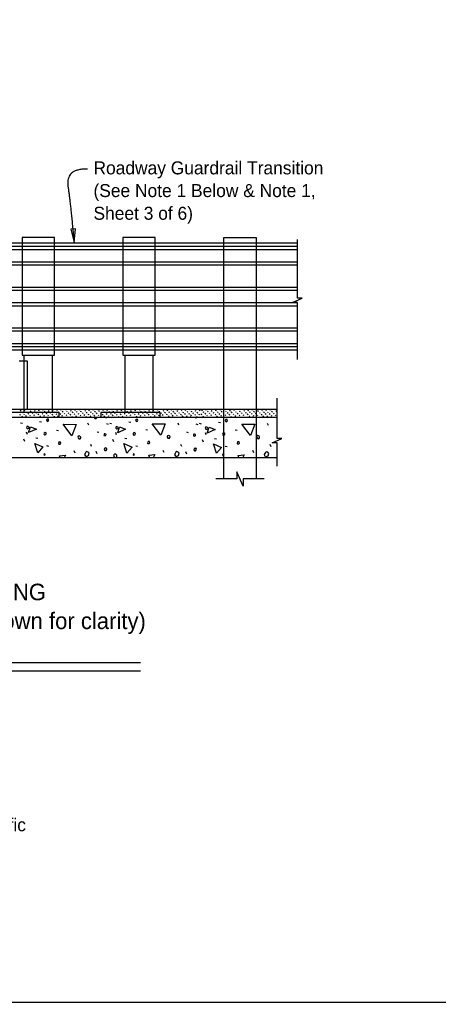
# Model space of a CAD drawing. Extents: x 1.5 to 68.7, y 0 to 31.1.
# Drawn here: x 14.15 to 20.65, y 1.78 to 17.03 of the extents above; entities that cross this region are included whole.
import ezdxf

# ---------------------------------------------------------------- set-up
doc = ezdxf.new("R2010")
doc.units = 0
for name, color, linetype in [('ActivePts-ConstElements', 7, 'Continuous'), ('AdhocPoint_dp', 7, 'Continuous'), ('Patterning', 7, 'Continuous'), ('PlotBorder_dp', 7, 'Continuous')]:
    doc.layers.add(name, color=color, linetype=linetype)

msp = doc.modelspace()

# ---------------------------------------------------------------- linework, layer by layer
at = {"layer": 'ActivePts-ConstElements'}
msp.add_lwpolyline([(1.467, 28.183), (42.533, 28.183), (42.533, 1.783), (1.467, 1.783)], close=True, dxfattribs=at)
at = {"layer": 'AdhocPoint_dp'}
for p, q in [((12.038, 7.055), (16.027, 7.055)), ((12.038, 6.925), (16.027, 6.925))]:
    msp.add_line(p, q, dxfattribs=at)
msp.add_lwpolyline([(14.995, 13.57), (15.016, 13.78), (14.945, 13.775)], close=True, dxfattribs=at)
for points in [[(18.46, 11.755), (18.46, 12.641), (18.382, 12.641), (18.532, 12.708), (18.46, 12.708), (18.46, 13.616)], [(18.144, 10.101), (18.144, 10.462), (18.067, 10.462), (18.217, 10.528), (18.144, 10.528), (18.144, 11.154)], [(17.945, 9.906), (17.619, 9.906), (17.619, 9.789), (17.52, 10.014), (17.52, 9.906), (17.195, 9.906)]]:
    msp.add_lwpolyline(points, dxfattribs=at)
msp.add_open_spline([(15.206, 14.708), (14.861, 14.721), (14.944, 14.148), (14.995, 13.57)], degree=2, dxfattribs=at)
at = {"layer": 'Patterning'}
for p, q in [((6.514, 13.565), (18.46, 13.565)), ((7.172, 13.512), (18.46, 13.512)), ((7.173, 13.464), (18.46, 13.464)), ((7.178, 13.271), (18.46, 13.271)), ((7.179, 13.223), (18.46, 13.223)), ((7.174, 12.831), (18.46, 12.831)), ((7.175, 12.879), (18.46, 12.879)), ((7.168, 12.59), (18.46, 12.59)), ((7.169, 12.638), (18.46, 12.638)), ((7.178, 12.198), (18.46, 12.198)), ((7.179, 12.246), (18.46, 12.246)), ((6.514, 11.904), (18.46, 11.904)), ((7.172, 11.957), (18.46, 11.957)), ((7.173, 12.005), (18.46, 12.005)), ((14.224, 10.932), (14.224, 11.821)), ((14.662, 10.932), (14.662, 11.821)), ((15.787, 10.932), (15.787, 11.821)), ((16.224, 10.932), (16.224, 11.821)), ((14.229, 10.963), (14.238, 10.977)), ((14.511, 10.968), (14.519, 10.982)), ((14.729, 10.965), (14.737, 10.979)), ((14.79, 10.967), (14.798, 10.981)), ((14.854, 10.975), (14.859, 10.985)), ((14.917, 10.983), (14.918, 10.985)), ((15.009, 10.963), (15.017, 10.977)), ((15.072, 10.971), (15.08, 10.985)), ((15.136, 10.98), (15.138, 10.985)), ((15.29, 10.968), (15.298, 10.982)), ((15.354, 10.976), (15.359, 10.985)), ((15.417, 10.984), (15.417, 10.985)), ((15.508, 10.965), (15.516, 10.979)), ((15.572, 10.973), (15.579, 10.985)), ((15.635, 10.981), (15.637, 10.985)), ((15.787, 10.97), (15.796, 10.984)), ((15.851, 10.978), (15.855, 10.985)), ((16.006, 10.967), (16.014, 10.981)), ((16.069, 10.975), (16.075, 10.985)), ((16.133, 10.983), (16.134, 10.985)), ((16.224, 10.963), (16.232, 10.977)), ((16.287, 10.971), (16.295, 10.985)), ((16.351, 10.98), (16.354, 10.985)), ((16.505, 10.968), (16.514, 10.982)), ((16.569, 10.976), (16.574, 10.985)), ((16.632, 10.984), (16.633, 10.985)), ((16.724, 10.965), (16.732, 10.979)), ((16.788, 10.973), (16.795, 10.984)), ((16.851, 10.981), (16.853, 10.984)), ((17.039, 10.97), (17.047, 10.984)), ((17.257, 10.967), (17.265, 10.981)), ((17.475, 10.963), (17.484, 10.977)), ((17.757, 10.968), (17.765, 10.982)), ((17.975, 10.965), (17.983, 10.979)), ((18.036, 10.967), (18.044, 10.981)), ((18.1, 10.975), (18.105, 10.985)), ((14.158, 10.892), (14.166, 10.906)), ((14.166, 10.955), (14.174, 10.969)), ((14.186, 10.864), (14.194, 10.878)), ((14.194, 10.928), (14.202, 10.942)), ((14.221, 10.9), (14.229, 10.914)), ((14.245, 10.859), (14.247, 10.862)), ((14.249, 10.872), (14.257, 10.886)), ((14.257, 10.936), (14.265, 10.95)), ((14.285, 10.908), (14.293, 10.922)), ((14.313, 10.88), (14.321, 10.894)), ((14.321, 10.944), (14.329, 10.958)), ((14.348, 10.916), (14.356, 10.93)), ((14.376, 10.888), (14.384, 10.902)), ((14.384, 10.952), (14.392, 10.966)), ((14.412, 10.924), (14.42, 10.938)), ((14.44, 10.896), (14.448, 10.91)), ((14.448, 10.96), (14.456, 10.974)), ((14.467, 10.869), (14.475, 10.883)), ((14.475, 10.932), (14.483, 10.946)), ((14.503, 10.905), (14.511, 10.919)), ((14.524, 10.859), (14.528, 10.867)), ((14.531, 10.877), (14.539, 10.891)), ((14.539, 10.94), (14.547, 10.954)), ((14.567, 10.913), (14.575, 10.927)), ((14.594, 10.885), (14.602, 10.899)), ((14.602, 10.948), (14.61, 10.962)), ((14.63, 10.921), (14.638, 10.935)), ((14.658, 10.893), (14.666, 10.907)), ((14.666, 10.957), (14.674, 10.971)), ((14.685, 10.865), (14.694, 10.879)), ((14.694, 10.929), (14.702, 10.943)), ((14.721, 10.901), (14.729, 10.915)), ((14.746, 10.867), (14.755, 10.881)), ((14.755, 10.931), (14.763, 10.945)), ((14.782, 10.903), (14.79, 10.917)), ((14.81, 10.876), (14.818, 10.89)), ((14.818, 10.939), (14.826, 10.953)), ((14.844, 10.86), (14.846, 10.862)), ((14.846, 10.911), (14.854, 10.925)), ((14.873, 10.884), (14.882, 10.898)), ((14.882, 10.947), (14.89, 10.961)), ((14.903, 10.86), (14.909, 10.87)), ((14.909, 10.919), (14.917, 10.933)), ((14.937, 10.892), (14.945, 10.906)), ((14.945, 10.955), (14.953, 10.969)), ((14.965, 10.864), (14.973, 10.878)), ((14.973, 10.928), (14.981, 10.942)), ((15, 10.9), (15.009, 10.914)), ((15.028, 10.872), (15.036, 10.886)), ((15.036, 10.936), (15.044, 10.95)), ((15.064, 10.908), (15.072, 10.922)), ((15.092, 10.88), (15.1, 10.894)), ((15.099, 10.856), (15.099, 10.856)), ((15.1, 10.944), (15.108, 10.958)), ((15.123, 10.86), (15.127, 10.867)), ((15.127, 10.916), (15.136, 10.93)), ((15.155, 10.888), (15.163, 10.902)), ((15.163, 10.952), (15.171, 10.966)), ((15.183, 10.861), (15.191, 10.875)), ((15.191, 10.924), (15.199, 10.938)), ((15.219, 10.896), (15.227, 10.91)), ((15.227, 10.96), (15.235, 10.974)), ((15.246, 10.869), (15.254, 10.883)), ((15.254, 10.932), (15.263, 10.946)), ((15.282, 10.905), (15.29, 10.919)), ((15.31, 10.877), (15.318, 10.891)), ((15.318, 10.94), (15.326, 10.954)), ((15.343, 10.86), (15.346, 10.863)), ((15.346, 10.913), (15.354, 10.927)), ((15.373, 10.885), (15.381, 10.899)), ((15.381, 10.948), (15.39, 10.962)), ((15.402, 10.86), (15.409, 10.871)), ((15.409, 10.921), (15.417, 10.935)), ((15.437, 10.893), (15.445, 10.907)), ((15.445, 10.957), (15.453, 10.971)), ((15.464, 10.865), (15.473, 10.879)), ((15.473, 10.929), (15.481, 10.943)), ((15.5, 10.901), (15.508, 10.915)), ((15.528, 10.874), (15.536, 10.888)), ((15.536, 10.937), (15.544, 10.951)), ((15.564, 10.909), (15.572, 10.923)), ((15.564, 10.86), (15.564, 10.86)), ((15.591, 10.882), (15.6, 10.896)), ((15.6, 10.945), (15.608, 10.959)), ((15.622, 10.86), (15.627, 10.868)), ((15.627, 10.917), (15.635, 10.931)), ((15.655, 10.89), (15.663, 10.904)), ((15.663, 10.953), (15.671, 10.967)), ((15.683, 10.862), (15.691, 10.876)), ((15.691, 10.926), (15.699, 10.94)), ((15.718, 10.898), (15.727, 10.912)), ((15.727, 10.961), (15.735, 10.975)), ((15.746, 10.87), (15.751, 10.879)), ((15.752, 10.934), (15.76, 10.948)), ((15.779, 10.907), (15.787, 10.921)), ((15.807, 10.879), (15.815, 10.893)), ((15.815, 10.942), (15.823, 10.956)), ((15.843, 10.915), (15.851, 10.929)), ((15.871, 10.887), (15.879, 10.901)), ((15.879, 10.951), (15.887, 10.965)), ((15.906, 10.923), (15.914, 10.937)), ((15.934, 10.895), (15.942, 10.909)), ((15.942, 10.959), (15.95, 10.973)), ((15.962, 10.867), (15.97, 10.881)), ((15.97, 10.931), (15.978, 10.945)), ((15.998, 10.903), (16.006, 10.917)), ((16.025, 10.876), (16.033, 10.89)), ((16.033, 10.939), (16.041, 10.953)), ((16.061, 10.911), (16.069, 10.925)), ((16.089, 10.884), (16.097, 10.898)), ((16.097, 10.947), (16.105, 10.961)), ((16.125, 10.919), (16.133, 10.933)), ((16.152, 10.892), (16.16, 10.906)), ((16.16, 10.955), (16.168, 10.969)), ((16.18, 10.864), (16.188, 10.878)), ((16.188, 10.928), (16.196, 10.942)), ((16.216, 10.9), (16.224, 10.914)), ((16.239, 10.86), (16.241, 10.862)), ((16.243, 10.872), (16.252, 10.886)), ((16.252, 10.936), (16.26, 10.95)), ((16.279, 10.908), (16.287, 10.922)), ((16.307, 10.88), (16.315, 10.894)), ((16.315, 10.944), (16.323, 10.958)), ((16.343, 10.916), (16.351, 10.93)), ((16.37, 10.888), (16.378, 10.902)), ((16.378, 10.952), (16.387, 10.966)), ((16.406, 10.924), (16.414, 10.938)), ((16.434, 10.896), (16.442, 10.91)), ((16.442, 10.96), (16.45, 10.974)), ((16.462, 10.869), (16.47, 10.883)), ((16.47, 10.932), (16.478, 10.946)), ((16.497, 10.905), (16.505, 10.919)), ((16.518, 10.86), (16.523, 10.867)), ((16.525, 10.877), (16.533, 10.891)), ((16.533, 10.94), (16.541, 10.954)), ((16.561, 10.913), (16.569, 10.927)), ((16.589, 10.885), (16.597, 10.899)), ((16.597, 10.948), (16.605, 10.962)), ((16.624, 10.921), (16.632, 10.935)), ((16.652, 10.893), (16.66, 10.907)), ((16.66, 10.957), (16.668, 10.971)), ((16.68, 10.865), (16.688, 10.879)), ((16.688, 10.929), (16.696, 10.943)), ((16.716, 10.901), (16.724, 10.915)), ((16.739, 10.859), (16.741, 10.863)), ((16.744, 10.873), (16.752, 10.887)), ((16.752, 10.937), (16.76, 10.951)), ((16.78, 10.909), (16.788, 10.923)), ((16.798, 10.859), (16.805, 10.871)), ((16.807, 10.882), (16.815, 10.896)), ((16.815, 10.945), (16.824, 10.959)), ((16.843, 10.917), (16.851, 10.931)), ((16.871, 10.89), (16.879, 10.904)), ((16.879, 10.953), (16.887, 10.967)), ((16.899, 10.862), (16.907, 10.876)), ((16.907, 10.925), (16.915, 10.939)), ((16.934, 10.898), (16.942, 10.912)), ((16.942, 10.961), (16.951, 10.975)), ((16.953, 10.855), (16.953, 10.855)), ((16.97, 10.898), (16.978, 10.912)), ((16.978, 10.961), (16.986, 10.975)), ((16.998, 10.87), (17.003, 10.879)), ((17.003, 10.934), (17.011, 10.948)), ((17.031, 10.907), (17.039, 10.921)), ((17.059, 10.879), (17.067, 10.893)), ((17.067, 10.942), (17.075, 10.956)), ((17.095, 10.915), (17.103, 10.929)), ((17.122, 10.887), (17.13, 10.901)), ((17.13, 10.951), (17.138, 10.964)), ((17.158, 10.923), (17.166, 10.937)), ((17.186, 10.895), (17.194, 10.909)), ((17.194, 10.959), (17.202, 10.973)), ((17.213, 10.867), (17.221, 10.881)), ((17.221, 10.931), (17.23, 10.945)), ((17.249, 10.903), (17.257, 10.917)), ((17.277, 10.876), (17.285, 10.89)), ((17.285, 10.939), (17.293, 10.953)), ((17.313, 10.911), (17.321, 10.925)), ((17.34, 10.884), (17.348, 10.898)), ((17.348, 10.947), (17.357, 10.961)), ((17.376, 10.919), (17.384, 10.933)), ((17.404, 10.892), (17.412, 10.906)), ((17.412, 10.955), (17.42, 10.969)), ((17.432, 10.864), (17.44, 10.878)), ((17.44, 10.928), (17.448, 10.942)), ((17.467, 10.9), (17.475, 10.914)), ((17.491, 10.859), (17.492, 10.862)), ((17.495, 10.872), (17.503, 10.886)), ((17.503, 10.936), (17.511, 10.95)), ((17.531, 10.908), (17.539, 10.922)), ((17.559, 10.88), (17.567, 10.894)), ((17.567, 10.944), (17.575, 10.958)), ((17.594, 10.916), (17.602, 10.93)), ((17.622, 10.888), (17.63, 10.902)), ((17.63, 10.952), (17.638, 10.966)), ((17.658, 10.924), (17.666, 10.938)), ((17.686, 10.896), (17.694, 10.91)), ((17.694, 10.96), (17.702, 10.974)), ((17.713, 10.869), (17.721, 10.883)), ((17.721, 10.932), (17.729, 10.946)), ((17.749, 10.905), (17.757, 10.919)), ((17.77, 10.859), (17.774, 10.867)), ((17.777, 10.877), (17.785, 10.891)), ((17.785, 10.94), (17.793, 10.954)), ((17.813, 10.913), (17.821, 10.927)), ((17.84, 10.885), (17.848, 10.899)), ((17.848, 10.948), (17.856, 10.962)), ((17.876, 10.921), (17.884, 10.935)), ((17.904, 10.893), (17.912, 10.907)), ((17.912, 10.957), (17.92, 10.971)), ((17.931, 10.865), (17.94, 10.879)), ((17.94, 10.929), (17.948, 10.943)), ((17.967, 10.901), (17.975, 10.915)), ((17.992, 10.867), (18.001, 10.881)), ((18.001, 10.931), (18.009, 10.945)), ((18.028, 10.903), (18.036, 10.917)), ((18.056, 10.876), (18.064, 10.89)), ((18.064, 10.939), (18.072, 10.953)), ((18.09, 10.86), (18.092, 10.862)), ((18.092, 10.911), (18.1, 10.925)), ((18.119, 10.884), (18.128, 10.898)), ((18.128, 10.947), (18.136, 10.961)), ((14.166, 10.773), (14.195, 10.766)), ((14.462, 10.792), (14.492, 10.787)), ((15.224, 10.734), (15.212, 10.768)), ((15.498, 10.761), (15.527, 10.754)), ((15.55, 10.77), (15.578, 10.763)), ((15.846, 10.789), (15.876, 10.784)), ((16.621, 10.734), (16.609, 10.768)), ((16.887, 10.756), (16.915, 10.749)), ((16.939, 10.765), (16.967, 10.758)), ((17.235, 10.784), (17.265, 10.779)), ((18.01, 10.73), (17.998, 10.763)), ((14.272, 10.592), (14.26, 10.626)), ((14.402, 10.538), (14.434, 10.534)), ((14.726, 10.66), (14.752, 10.655)), ((15.352, 10.635), (15.378, 10.63)), ((15.656, 10.589), (15.644, 10.622)), ((15.786, 10.534), (15.817, 10.531)), ((16.108, 10.668), (16.135, 10.663)), ((16.74, 10.631), (16.767, 10.625)), ((17.045, 10.584), (17.033, 10.618)), ((17.174, 10.53), (17.206, 10.526)), ((17.497, 10.664), (17.524, 10.658)), ((14.23, 10.483), (14.216, 10.518)), ((14.57, 10.419), (14.598, 10.412)), ((15.268, 10.404), (15.254, 10.439)), ((15.614, 10.479), (15.599, 10.514)), ((15.953, 10.416), (15.982, 10.409)), ((16.666, 10.404), (16.651, 10.439)), ((17.003, 10.475), (16.988, 10.51)), ((17.342, 10.411), (17.371, 10.404)), ((18.054, 10.399), (18.04, 10.434)), ((15.012, 10.303), (14.998, 10.338)), ((15.356, 10.292), (15.341, 10.327)), ((16.394, 10.311), (16.38, 10.346)), ((16.744, 10.287), (16.73, 10.323)), ((17.783, 10.307), (17.769, 10.342))]:
    msp.add_line(p, q, dxfattribs=at)
for points in [[(14.193, 11.821), (14.693, 11.821), (14.693, 13.648), (14.193, 13.648)], [(15.755, 11.821), (16.255, 11.821), (16.255, 13.648), (15.755, 13.648)], [(13.85, 10.859), (14.766, 10.859), (14.766, 10.932), (13.85, 10.932)], [(15.412, 10.859), (16.329, 10.859), (16.329, 10.932), (15.412, 10.932)]]:
    msp.add_lwpolyline(points, close=True, dxfattribs=at)
for points in [[(17.32, 9.906), (17.32, 13.648), (17.82, 13.648), (17.82, 9.906)], [(14.573, 10.805), (14.584, 10.794), (14.595, 10.801), (14.602, 10.812), (14.598, 10.829), (14.589, 10.831), (14.577, 10.829), (14.566, 10.819), (14.573, 10.805)], [(15.306, 10.856), (15.316, 10.84), (15.339, 10.842), (15.348, 10.851), (15.353, 10.856)], [(15.495, 10.846), (15.492, 10.856)], [(15.5, 10.856), (15.495, 10.846)], [(15.957, 10.801), (15.968, 10.791), (15.978, 10.798), (15.985, 10.808), (15.982, 10.826), (15.973, 10.828), (15.961, 10.826), (15.95, 10.815), (15.957, 10.801)], [(16.884, 10.842), (16.881, 10.852)], [(16.889, 10.852), (16.884, 10.842)], [(14.269, 10.685), (14.281, 10.683), (14.294, 10.688), (14.297, 10.699), (14.292, 10.708), (14.281, 10.715), (14.269, 10.72), (14.262, 10.706), (14.258, 10.696), (14.269, 10.685)], [(14.291, 10.621), (14.319, 10.713), (14.413, 10.676), (14.291, 10.621)], [(14.961, 10.573), (14.827, 10.75), (15.026, 10.748), (14.961, 10.573)], [(15.652, 10.681), (15.665, 10.68), (15.677, 10.685), (15.681, 10.696), (15.675, 10.704), (15.665, 10.712), (15.652, 10.717), (15.645, 10.703), (15.642, 10.692), (15.652, 10.681)], [(15.674, 10.617), (15.702, 10.709), (15.796, 10.672), (15.674, 10.617)], [(16.343, 10.581), (16.209, 10.758), (16.409, 10.756), (16.343, 10.581)], [(17.041, 10.677), (17.054, 10.675), (17.066, 10.681), (17.07, 10.691), (17.064, 10.7), (17.054, 10.707), (17.041, 10.712), (17.034, 10.698), (17.031, 10.688), (17.041, 10.677)], [(17.063, 10.613), (17.091, 10.705), (17.185, 10.668), (17.063, 10.613)], [(17.346, 10.797), (17.357, 10.786), (17.367, 10.793), (17.374, 10.804), (17.371, 10.822), (17.362, 10.823), (17.349, 10.822), (17.339, 10.811), (17.346, 10.797)], [(17.732, 10.577), (17.598, 10.754), (17.798, 10.752), (17.732, 10.577)], [(14.538, 10.585), (14.545, 10.585), (14.559, 10.593), (14.565, 10.608), (14.563, 10.617), (14.549, 10.624), (14.531, 10.614), (14.527, 10.603), (14.531, 10.593), (14.538, 10.585)], [(15.06, 10.541), (15.069, 10.525), (15.09, 10.522), (15.099, 10.538), (15.102, 10.552), (15.093, 10.561), (15.078, 10.57), (15.062, 10.564), (15.056, 10.548), (15.06, 10.541)], [(15.459, 10.577), (15.479, 10.571), (15.491, 10.58), (15.493, 10.593), (15.489, 10.596), (15.475, 10.603), (15.463, 10.601), (15.461, 10.589), (15.459, 10.577)], [(15.922, 10.582), (15.929, 10.582), (15.943, 10.589), (15.948, 10.605), (15.946, 10.614), (15.932, 10.621), (15.915, 10.61), (15.911, 10.6), (15.915, 10.589), (15.922, 10.582)], [(16.442, 10.55), (16.451, 10.534), (16.472, 10.53), (16.481, 10.546), (16.485, 10.56), (16.476, 10.569), (16.46, 10.578), (16.444, 10.573), (16.439, 10.557), (16.442, 10.55)], [(16.848, 10.572), (16.868, 10.567), (16.88, 10.576), (16.882, 10.588), (16.878, 10.592), (16.864, 10.599), (16.852, 10.597), (16.85, 10.585), (16.848, 10.572)], [(17.311, 10.578), (17.318, 10.578), (17.332, 10.585), (17.337, 10.601), (17.335, 10.609), (17.321, 10.617), (17.303, 10.606), (17.3, 10.595), (17.303, 10.585), (17.311, 10.578)], [(17.831, 10.545), (17.84, 10.529), (17.861, 10.526), (17.87, 10.542), (17.874, 10.556), (17.865, 10.565), (17.849, 10.574), (17.833, 10.568), (17.828, 10.552), (17.831, 10.545)], [(14.433, 10.308), (14.386, 10.454), (14.511, 10.399), (14.433, 10.308)], [(14.758, 10.444), (14.779, 10.444), (14.789, 10.455), (14.784, 10.474), (14.761, 10.476), (14.758, 10.465), (14.752, 10.457), (14.758, 10.444), (14.754, 10.448)], [(15.465, 10.359), (15.474, 10.343), (15.493, 10.345), (15.502, 10.357), (15.504, 10.377), (15.492, 10.382), (15.483, 10.384), (15.472, 10.38), (15.469, 10.377), (15.465, 10.359)], [(15.817, 10.304), (15.769, 10.451), (15.895, 10.396), (15.817, 10.304)], [(16.14, 10.452), (16.161, 10.452), (16.172, 10.463), (16.166, 10.482), (16.143, 10.484), (16.14, 10.474), (16.135, 10.465), (16.14, 10.452), (16.136, 10.456)], [(16.854, 10.354), (16.863, 10.339), (16.882, 10.34), (16.891, 10.353), (16.893, 10.372), (16.881, 10.377), (16.872, 10.379), (16.861, 10.376), (16.858, 10.372), (16.854, 10.354)], [(17.206, 10.3), (17.158, 10.446), (17.284, 10.392), (17.206, 10.3)], [(17.529, 10.448), (17.55, 10.448), (17.561, 10.459), (17.555, 10.478), (17.532, 10.48), (17.529, 10.469), (17.524, 10.46), (17.529, 10.448), (17.525, 10.452)], [(14.532, 10.272), (14.552, 10.281), (14.545, 10.288), (14.532, 10.293), (14.527, 10.281), (14.532, 10.272)], [(14.781, 10.231), (14.772, 10.26), (14.865, 10.273), (14.844, 10.231)], [(15.166, 10.266), (15.189, 10.253), (15.219, 10.266), (15.231, 10.303), (15.214, 10.32), (15.191, 10.326), (15.18, 10.319), (15.168, 10.299), (15.159, 10.283), (15.166, 10.266)], [(15.642, 10.231), (15.652, 10.239), (15.66, 10.249), (15.66, 10.27), (15.644, 10.286), (15.624, 10.285), (15.615, 10.276), (15.61, 10.26)], [(15.61, 10.26), (15.621, 10.239), (15.633, 10.231)], [(15.916, 10.269), (15.935, 10.278), (15.928, 10.285), (15.916, 10.29), (15.911, 10.278), (15.916, 10.269)], [(16.164, 10.239), (16.154, 10.269), (16.248, 10.281), (16.226, 10.239)], [(16.563, 10.266), (16.586, 10.253), (16.616, 10.266), (16.628, 10.303), (16.611, 10.32), (16.588, 10.326), (16.577, 10.319), (16.565, 10.299), (16.556, 10.283), (16.563, 10.266)], [(17.305, 10.264), (17.324, 10.273), (17.317, 10.28), (17.305, 10.286), (17.3, 10.273), (17.305, 10.264)], [(17.552, 10.235), (17.543, 10.264), (17.637, 10.277), (17.615, 10.235)], [(17.952, 10.261), (17.975, 10.249), (18.005, 10.261), (18.017, 10.298), (18, 10.316), (17.977, 10.321), (17.966, 10.314), (17.954, 10.295), (17.945, 10.279), (17.952, 10.261)]]:
    msp.add_lwpolyline(points, dxfattribs=at)
at = {"layer": 'PlotBorder_dp'}
for p, q in [((14.146, 11.734), (14.271, 11.734)), ((14.271, 11.735), (14.271, 10.985)), ((3.872, 10.984), (18.144, 10.984)), ((11.816, 10.859), (18.144, 10.859)), ((9.092, 10.234), (18.144, 10.234))]:
    msp.add_line(p, q, dxfattribs=at)

# ---------------------------------------------------------------- texts
at = {"layer": 'AdhocPoint_dp'}
for s, height, p in [('Roadway Guardrail Transition', 0.2016, (15.297, 14.627)), ('(See Note 1 Below & Note 1,', 0.2016, (15.297, 14.275)), ('Sheet 3 of 6)', 0.2016, (15.297, 13.923)), ('PARTIAL ELEVATION OF INSIDE FACE OF RAILING', 0.256, (6.267, 8.021)), ('(Existing Wing Post, Railing Reinforcing and Expansion Dowel Assemblies not shown for clarity)', 0.256, (1.573, 7.573)), ('1. See Roadway Plans for limiting station of Roadway Guardrail Transition or other site specific', 0.2016, (2.937, 4.436))]:
    msp.add_text(s, height=height, dxfattribs=at).set_placement(p)

doc.saveas('drawing.dxf')
